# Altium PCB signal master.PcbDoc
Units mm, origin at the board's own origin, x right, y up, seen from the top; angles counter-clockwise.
Board outline 271.14 x 200.15 mm, 2 copper layers (Top Layer, Bottom Layer), stack 1.639 mm thick; 60 components, 36 nets, 314 pads, 143 vias.
Unrouted connection lines stored in the file: 4.
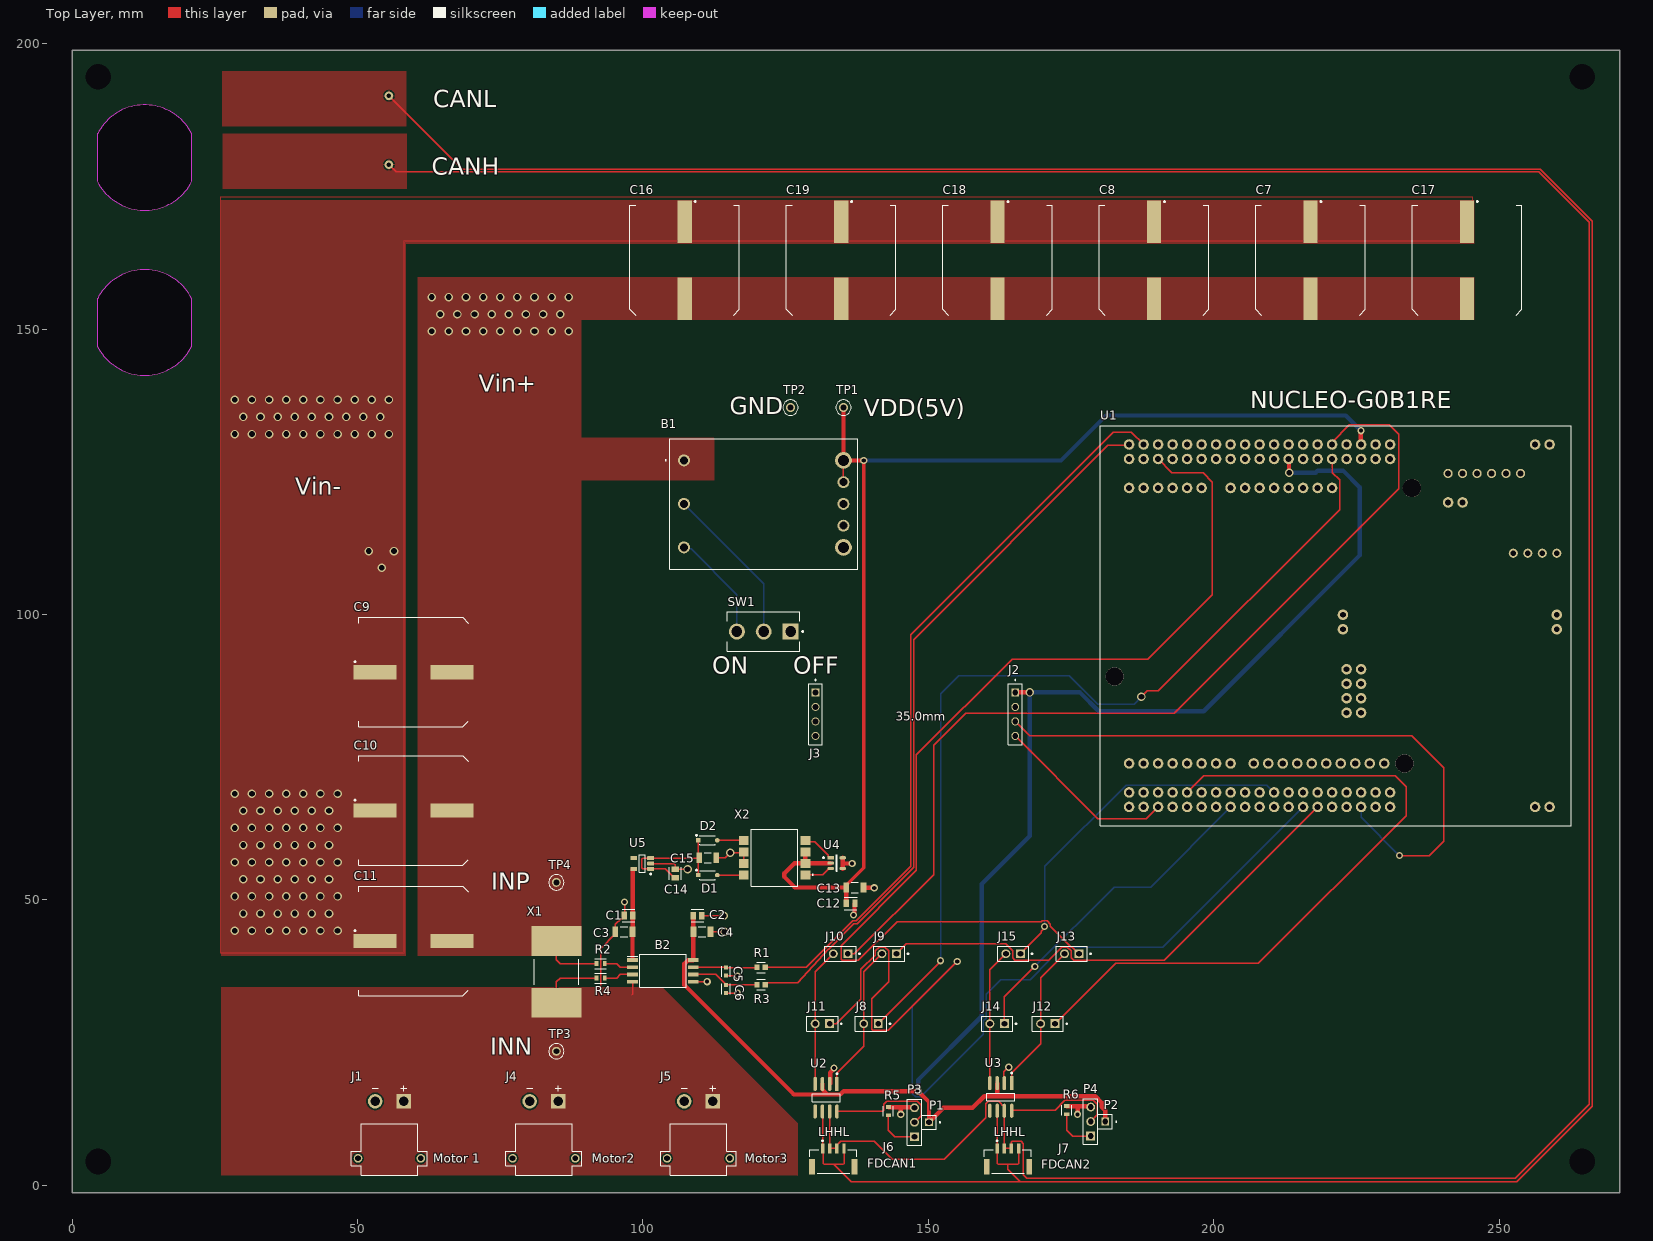
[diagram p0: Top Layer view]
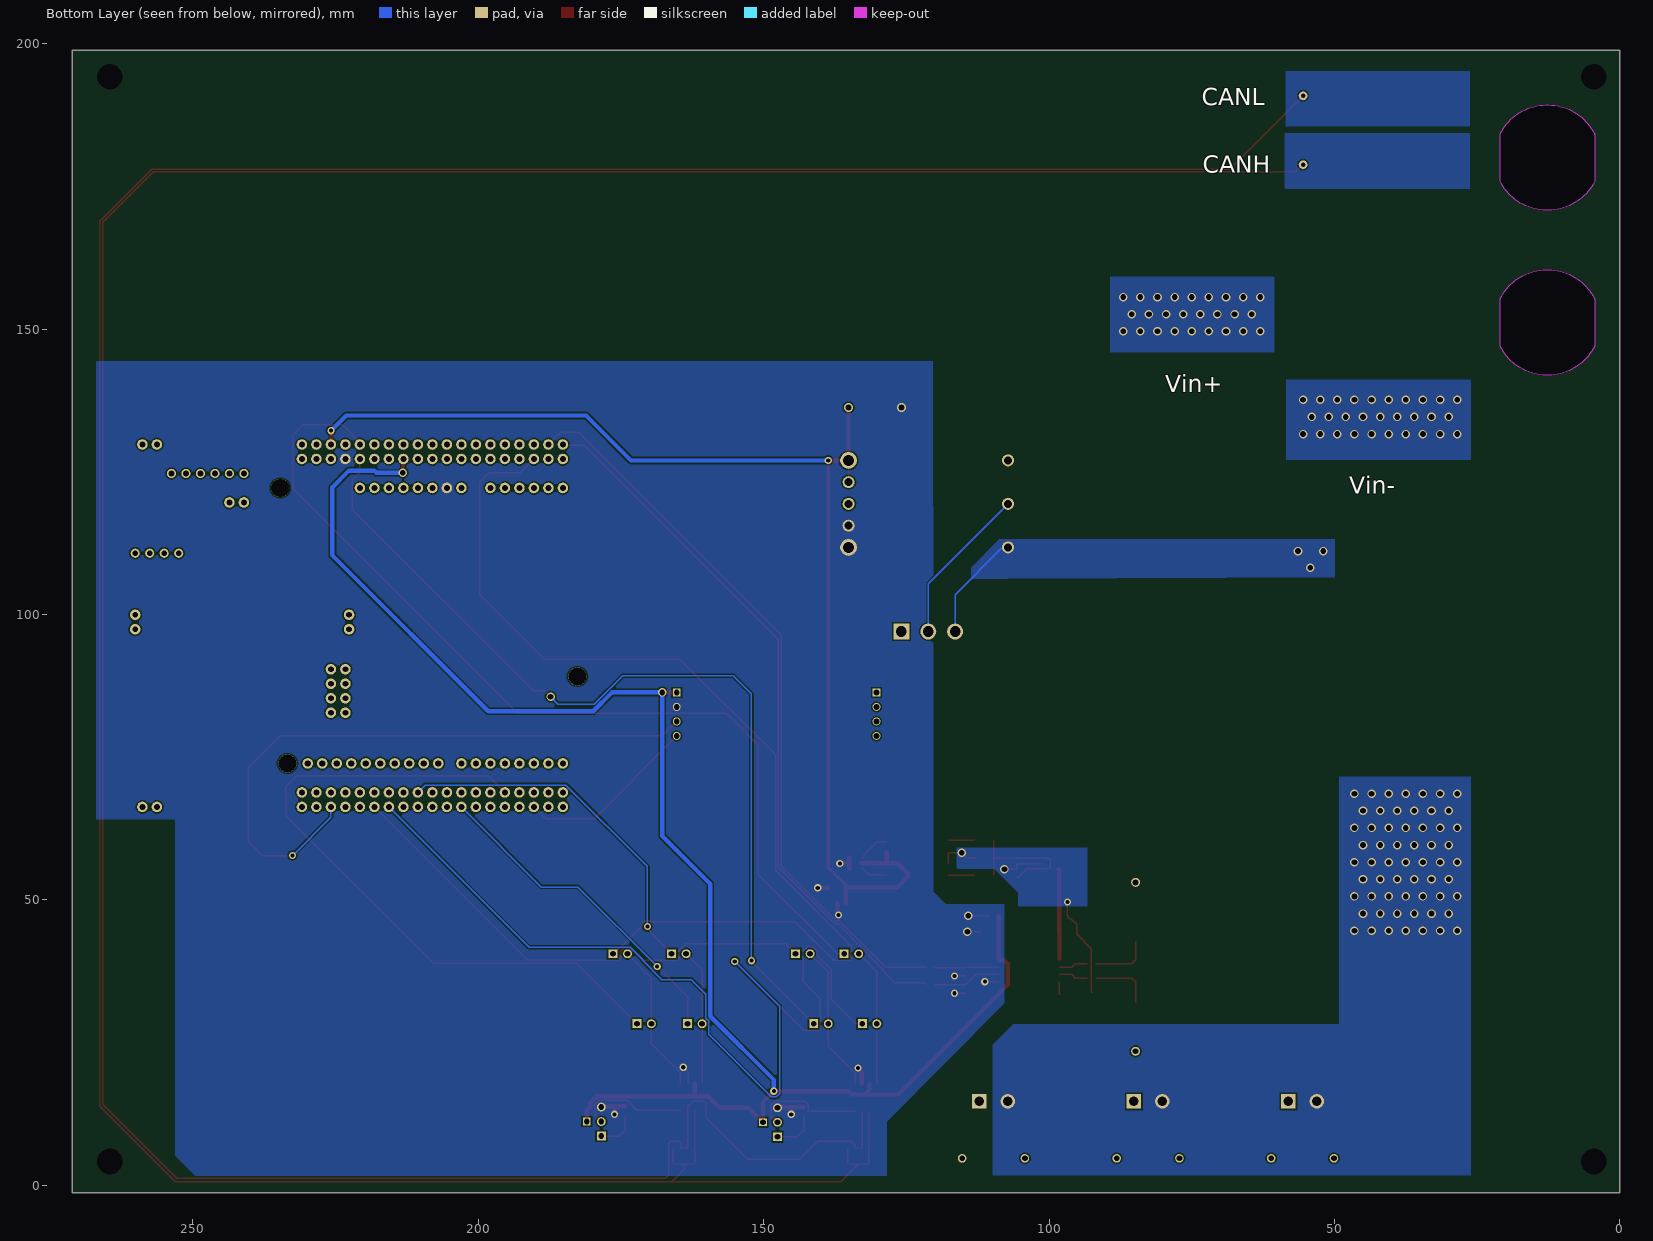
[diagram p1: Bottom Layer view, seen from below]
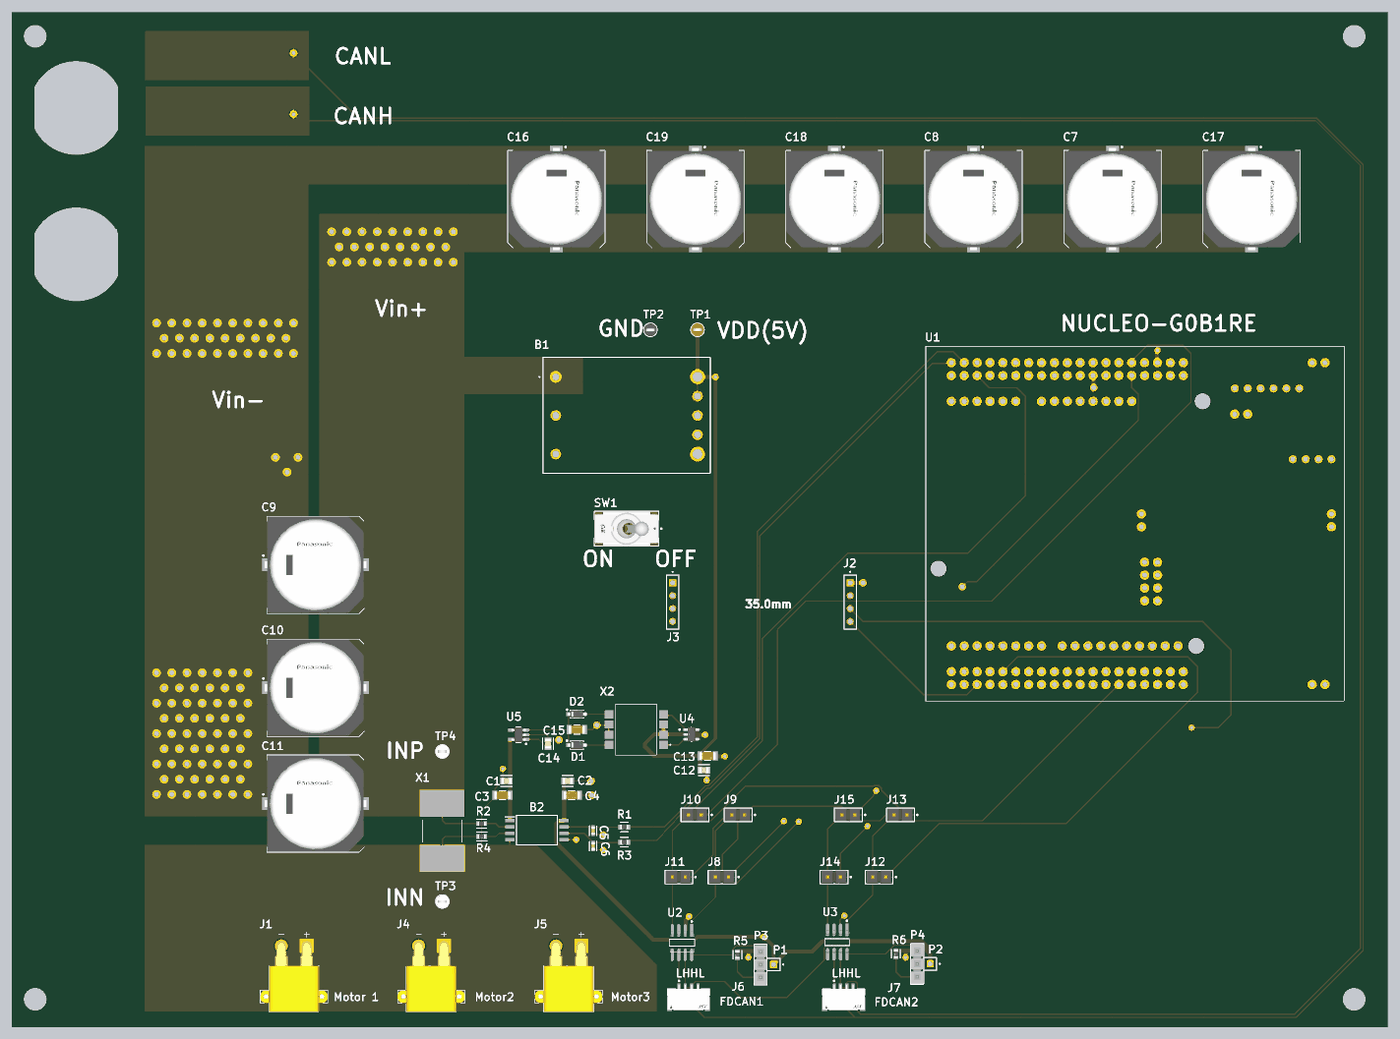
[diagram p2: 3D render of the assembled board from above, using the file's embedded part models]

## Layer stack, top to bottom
Top Solder: solder mask 0.0102, Solder Resist, Dk 3.5
Top Layer: signal copper 0.07
Dielectric 1: core 1.4986, Core-043, Dk 4.3
Bottom Layer: signal copper 0.07
Bottom Solder: solder mask 0.0102, Solder Resist, Dk 3.5

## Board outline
0,198.882 271.145,198.882 271.145,-1.27 0,-1.27
cut-out: 4.44,147.005 ccw(c12.7,151.168) 20.953,146.991 20.955,147.01 20.955,155.321 20.954,155.343 ccw(c12.7,151.168) 4.451,155.353 4.445,155.333
cut-out: 4.44,175.883 ccw(c12.7,180.046) 20.953,175.869 20.955,175.888 20.955,184.199 20.954,184.221 ccw(c12.7,180.046) 4.451,184.231 4.445,184.211

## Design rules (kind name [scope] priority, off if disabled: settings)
AssemblyTestPointUsage [All] p1: isadvanced=TRUE
AssemblyTestpoint [All] p1: isadvanced=TRUE testpointundercomponent=TRUE minsize=1.016 maxsize=2.54 preferedsize=1.524 minholesize=0 maxholesize=1.016 preferedholesize=0.813 testpointgrid=0.025 usegrid=TRUE gridtolerance=0 allowsidetop=TRUE allowsidebottom=TRUE
Clearance "Stitching Vin-" [IsStitchingVia and InNet('Vin-') vs (IsVia and (Not IsStitchingVia)) Or IsPad] p1: isadvanced=TRUE gap=0.127 ignorepadtopadclearanceinfootprint=FALSE
Clearance Clearance_1 [OnMid vs OnMid] p2: gap=0.254 ignorepadtopadclearanceinfootprint=FALSE sourcerule=55 cellrowname=All cellrowtype=0 cellcolname=All cellcoltype=0 innerlayers=TRUE
Clearance Clearance_2 [(ExistsOnLayer('Top Layer') Or ExistsOnLayer('Bottom Layer')) vs (ExistsOnLayer('Top Layer') Or ExistsOnLayer('Bottom Layer'))] p3: gap=0.254 ignorepadtopadclearanceinfootprint=FALSE sourcerule=55 cellrowname=All cellrowtype=0 cellcolname=All cellcoltype=0 outerlayers=TRUE
Clearance [All] p4: gap=0.254 ignorepadtopadclearanceinfootprint=FALSE ismatrix=TRUE
ComponentClearance [All] p1: isadvanced=TRUE gap=0.254 collisioncheckmode=3 verticalgap=0.254 showdistances=FALSE
FabricationTestPointUsage [All] p1: isadvanced=TRUE valid=0 allowmultiple=FALSE
FabricationTestpoint [All] p1: isadvanced=TRUE side=3 testpointundercomponent=TRUE minsize=1.016 maxsize=2.54 preferedsize=1.524 minholesize=0 maxholesize=1.016 preferedholesize=0.813 testpointgrid=0.025 allowsidetop=TRUE allowsidebottom=TRUE usegrid=TRUE gridtolerance=0
FanoutControl Fanout_BGA [IsBGA] p1: isadvanced=TRUE bgadir=Out bgaviamode=Centered fanoutstyle=Auto fanoutdirection=Alternating viagrid=0.025 // Fanout_BGA (Default Rule)
FanoutControl Fanout_LCC [IsLCC] p2: isadvanced=TRUE bgadir=Out bgaviamode=Centered fanoutstyle=Auto fanoutdirection=Alternating viagrid=0.025 // Fanout_LCC (Default Rule)
FanoutControl Fanout_SOIC [IsSOIC] p3: isadvanced=TRUE bgadir=Out bgaviamode=Centered fanoutstyle=Auto fanoutdirection=Alternating viagrid=0.025 // Fanout_SOIC (Default Rule)
FanoutControl Fanout_Small [(CompPinCount < 5)] p4: isadvanced=TRUE bgadir=Out bgaviamode=Centered fanoutstyle=Auto fanoutdirection=OutThenIn viagrid=0.025 // Fanout_Small (Default Rule)
FanoutControl Fanout_Default [All] p5: isadvanced=TRUE bgadir=Out bgaviamode=Centered fanoutstyle=Auto fanoutdirection=Alternating viagrid=0.025 // Fanout_Default (Default Rule)
Height [All] p1: isadvanced=TRUE minheight=0 maxheight=25.4 prefheight=12.7
HoleSize [All] p1: isadvanced=TRUE absolutevalues=TRUE maxlimit=5 minlimit=0.025 maxpercent=80.000 minpercent=20.000
HoleToHoleClearance [All] p1: isadvanced=TRUE gap=0.254 allowstackedmicrovias=TRUE
LayerPairs [All] p1: isadvanced=TRUE enforce=TRUE
MinimumSolderMaskSliver [All] p1: isadvanced=TRUE minsoldermaskwidth=0.05
NetAntennae [All] p1: isadvanced=TRUE netantennaetolerance=0
PasteMaskExpansion [All] p1: isadvanced=TRUE expansion=0
PlaneClearance [All] p1: isadvanced=TRUE clearance=0.508
PlaneConnect [All] p1: isadvanced=TRUE planeconnectstyle=Relief reliefexpansion=0.508 reliefentries=4 reliefconductorwidth=0.254 reliefairgap=0.254
PolygonConnect "Schematic Polygon Connect Style_5" [InNet('GND')] p1: connectstyle=Direct reliefconductorwidth=0.254 reliefentries=4 polygonreliefangle="90 Angle" airgapwidth=0.254
PolygonConnect "Schematic Polygon Connect Style_4" [InNet('INP')] p2: connectstyle=Direct reliefconductorwidth=0.254 reliefentries=4 polygonreliefangle="90 Angle" airgapwidth=0.254
PolygonConnect "Schematic Polygon Connect Style_3" [InNet('VDD')] p3: connectstyle=Direct reliefconductorwidth=0.254 reliefentries=4 polygonreliefangle="90 Angle" airgapwidth=0.254
PolygonConnect "Schematic Polygon Connect Style_2" [InNet('AVDD')] p4: connectstyle=Direct reliefconductorwidth=0.254 reliefentries=4 polygonreliefangle="90 Angle" airgapwidth=0.254
PolygonConnect "Schematic Polygon Connect Style_1" [InNet('Vin-')] p5: connectstyle=Direct reliefconductorwidth=0.254 reliefentries=4 polygonreliefangle="90 Angle" airgapwidth=0.254
PolygonConnect "Schematic Polygon Connect Style" [InNet('VCC')] p6: connectstyle=Direct reliefconductorwidth=0.254 reliefentries=4 polygonreliefangle="90 Angle" airgapwidth=0.254
PolygonConnect PolygonConnectStyle_1 [InNet('INN')] p7: connectstyle=Direct reliefconductorwidth=0.254 reliefentries=4 polygonreliefangle="90 Angle" airgapwidth=0.254
PolygonConnect [All] p8: connectstyle=Relief reliefconductorwidth=0.254 reliefentries=4 polygonreliefangle="90 Angle" airgapwidth=0.254
RoutingCorners [All] p1: isadvanced=TRUE cornerstyle=45-Degree minsetback=2.54 maxsetback=2.54
RoutingPriority [All] p1: isadvanced=TRUE routingpriority=0
RoutingVias [All] p1: holewidth=1 width=1.5 viastyle="Through Hole" minholewidth=1 minwidth=1.5 maxholewidth=1 maxwidth=1.5
ShortCircuit [All] p1: isadvanced=TRUE allowed=FALSE
SilkToSilkClearance [All] p1: isadvanced=TRUE silktosilkclearance=0.254
SilkToSolderMaskClearance [IsPad] p1: isadvanced=TRUE minsilkscreentomaskgap=0.1 clearancetoexposedcopper=TRUE
SolderMaskExpansion [All] p1: isadvanced=TRUE expansion=0.102 istentingtop=FALSE
SupplyNets "Schematic Supply Nets_2" [InNet('Vin-')] p1: isadvanced=TRUE voltage=0.000
SupplyNets "Schematic Supply Nets_7" [InNet('INN')] p2: isadvanced=TRUE voltage=0.000
SupplyNets "Schematic Supply Nets_4" [InNet('INP')] p3: isadvanced=TRUE voltage=0.000
SupplyNets "Schematic Supply Nets_6" [InNet('VDD')] p4: isadvanced=TRUE voltage=0.000
SupplyNets "Schematic Supply Nets_5" [InNet('GND')] p5: isadvanced=TRUE voltage=0.000
SupplyNets "Schematic Supply Nets_1" [InNet('VCC')] p6: isadvanced=TRUE voltage=0.000
SupplyNets "Schematic Supply Nets" [InNet('AVDD')] p7: isadvanced=TRUE voltage=0.000
UnRoutedNet [All] p1: isadvanced=TRUE
UnpouredPolygon [All] p1: isadvanced=TRUE
Width MaxMinWidth_2 [InNet('GND')] p1: maxlimit=1 minlimit=0.2 preferedwidth=0.6 minimp=50.000000 maximp=50.000000 favimp=50.000000
Width MaxMinWidth_1 [InNet('VDD')] p2: maxlimit=1 minlimit=0.2 preferedwidth=0.6 minimp=50.000000 maximp=50.000000 favimp=50.000000
Width MaxMinWidth_4 [InNet('AVDD')] p3: maxlimit=1 minlimit=0.2 preferedwidth=0.6 minimp=50.000000 maximp=50.000000 favimp=50.000000
Width MaxMinWidth_3 [InNet('VCC')] p4: maxlimit=1 minlimit=0.2 preferedwidth=0.6 minimp=50.000000 maximp=50.000000 favimp=50.000000
Width [All] p5: maxlimit=0.254 minlimit=0.254 preferedwidth=0.254
4 further rules are at their usual default settings.

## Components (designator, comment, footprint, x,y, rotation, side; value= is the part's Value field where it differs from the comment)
B1 "ULS-5_20-D48N-C" ULS520D48NC 107.188,127 r0 top
B2 "AMC1306M25QDWVRQ1" SOIC127P1150X280-8N 103.496,37.592 r0 top
C1 "C0805C106K8PACTU" FP-C0805C-DG-MFG 97.471,47.268 r0 top value=10uF
C2 "C0805C106K8PACTU" FP-C0805C-DG-MFG 109.539,47.261 r180 top value=10uF
C3 "CC1206KRX7R9BB104" FP-CC1206-1_25-MFG 96.671,44.45 r0 top value="100 nF"
C4 "CC1206KRX7R9BB104" FP-CC1206-1_25-MFG 110.339,44.45 r180 top value="100 nF"
C5 "CGA3E2NP01H330J080AA" FP-CGA3E-0_3-0_1-MFG 114.554,37.465 r270 top
C6 "CGA3E2NP01H330J080AA" FP-CGA3E-0_3-0_1-MFG 114.554,34.417 r270 top
C7 "EEV-TG2A221M" FP-TG-K16-MFG 216.941,162.071 r270 top
C8 "EEV-TG2A221M" FP-TG-K16-MFG 189.535,162.071 r270 top
C9 "EEV-TG2A221M" FP-TG-K16-MFG 59.817,89.916 r0 top
C10 "EEV-TG2A221M" FP-TG-K16-MFG 59.817,65.659 r0 top
C11 "EEV-TG2A221M" FP-TG-K16-MFG 59.817,42.799 r0 top
C12 "C0805C106K8PACTU" FP-C0805C-DG-MFG 136.398,49.403 r180 top value=10uF
C13 "CC1206KRX7R9BB104" FP-CC1206-1_25-MFG 137.136,52.197 r180 top value="100 nF"
C14 "C0805C106K8PACTU" FP-C0805C-DG-MFG 105.664,54.622 r90 top value=10uF
C15 "CC1206KRX7R9BB104" FP-CC1206-1_25-MFG 111.355,57.404 r0 top value="100 nF"
C16 "EEV-TG2A221M" FP-TG-K16-MFG 107.315,162.071 r270 top
C17 "EEV-TG2A221M" FP-TG-K16-MFG 244.348,162.071 r270 top
C18 "EEV-TG2A221M" FP-TG-K16-MFG 162.128,162.071 r270 top
C19 "EEV-TG2A221M" FP-TG-K16-MFG 134.722,162.071 r270 top
D1 "MBR0520LT1G" FP-425-04-IPC_C 111.339,54.356 r0 top
D2 "MBR0520LT1G" FP-425-04-IPC_C 111.339,60.452 r0 top
J1 "XT30PW-M" AMASS_XT30PW-M 55.587,4.73 r180 top
J2 "SSW-104-01-T-S" SAMTEC_SSW-104-01-T-S 165.227,86.36 r270 top
J3 "SSW-104-01-T-S" SAMTEC_SSW-104-01-T-S 130.229,86.36 r270 top
J4 "XT30PW-M" AMASS_XT30PW-M 82.658,4.73 r180 top
J5 "XT30PW-M" AMASS_XT30PW-M 109.728,4.73 r180 top
J6 "SM04B-GHS-TB(LF)(SN)" FP-SM04B-GHS-TB_LF_SN-MFG 133.35,4.191 r0 top
J7 "SM04B-GHS-TB(LF)(SN)" FP-SM04B-GHS-TB_LF_SN-MFG 163.932,4.191 r0 top
J8 "TSW-102-07-G-S" FP-TSW-102-07-G-S-MFG 139.954,28.321 r180 top
J9 "TSW-102-07-G-S" FP-TSW-102-07-G-S-MFG 143.129,40.581 r180 top
J10 "TSW-102-07-G-S" FP-TSW-102-07-G-S-MFG 134.62,40.581 r180 top
J11 "TSW-102-07-G-S" FP-TSW-102-07-G-S-MFG 131.445,28.321 r180 top
J12 "TSW-102-07-G-S" FP-TSW-102-07-G-S-MFG 170.942,28.321 r180 top
J13 "TSW-102-07-G-S" FP-TSW-102-07-G-S-MFG 175.133,40.581 r180 top
J14 "TSW-102-07-G-S" FP-TSW-102-07-G-S-MFG 162.052,28.321 r180 top
J15 "TSW-102-07-G-S" FP-TSW-102-07-G-S-MFG 164.846,40.581 r180 top
P1 "HTSW-101-07-L-S" SAMTEC_HTSW-101-07-L-S 150.114,11.049 r0 top
P2 "HTSW-101-07-L-S" SAMTEC_HTSW-101-07-L-S 180.975,11.176 r0 top
P3 "TSW-103-07-G-S" SMTC-TSW-103-07-X-S 147.574,8.509 r90 top
P4 "TSW-103-07-G-S" SMTC-TSW-103-07-X-S 178.435,8.636 r90 top
R1 "CRCW0603100RJNEA" FP-CRCW0603-e3-IPC_B 120.697,38.196 r0 top
R2 "ERJ-3GEY0R00V" FP-ERJ-3GEY0R00V-MFG 92.583,38.862 r0 top value=0Ω
R3 "CRCW0603100RJNEA" FP-CRCW0603-e3-IPC_B 120.697,35.179 r180 top
R4 "ERJ-3GEY0R00V" FP-ERJ-3GEY0R00V-MFG 92.583,36.322 r180 top value=0Ω
R5 "RMCF0603FT10K0" FP-RMCF0603-MFG 143.002,12.991 r270 top
R6 "RMCF0603FT10K0" FP-RMCF0603-MFG 174.244,13.171 r270 top
SW1 "7101SD9CQE" FP-7101SD9CQE-MFG 121.158,97.028 r270 top
TP1 "5000" FP-5000-MFG 135.128,136.271 r0 top
TP2 "5001" FP-5001-MFG 125.857,136.271 r0 top
TP3 "5002" FP-5002-MFG 84.836,23.495 r0 top
TP4 "5002" FP-5002-MFG 84.836,53.086 r0 top
U1 "NUCLEO-G0B1RE" MODULE_NUCLEO-G0B1RE 221.376,98.044 r270 top
U2 "SN65HVD230DR" FP-D0008A-IPC_A 132.08,15.368 r270 top
U3 "SN65HVD230DR" FP-D0008A-IPC_A 162.687,15.495 r270 top
U4 "SN6501DBVR" FP-DBV0005A-IPC_C 133.951,56.449 r0 top
U5 "TPS76350DBVR" DBV0005A_M 99.871,56.388 r180 top
X1 "WSLP59311L000FEB" WSLP59311L000FEB 84.836,37.404 r90 top
X2 "DA2303-ALD" DA2303ALD 123.063,57.404 r180 top

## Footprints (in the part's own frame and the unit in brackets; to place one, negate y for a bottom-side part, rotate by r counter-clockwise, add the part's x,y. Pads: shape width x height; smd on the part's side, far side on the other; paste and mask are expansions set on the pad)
AMASS_XT30PW-M [mm]
  round 2.55 hole 1.7: N(2.5,-10)
  rect 2.55x2.55 / inner round 2.55 / far side rect 2.55x2.55 hole 1.7: P(-2.5,-10)
  round 1.508 hole 1: S1(5.5,0) S2(-5.5,0)
  silkscreen extent -6.65,-12.75 6.65,2.95, body extent -6.65,-11 6.65,2.95, height 5
DA2303ALD [mm]
  rect 1.7x1.6 smd: 1(-5.4,3) 2(-5.4,1) 3(-5.4,-1) 4(-5.4,-3) 5(5.4,-3) 6(5.4,-1) 7(5.4,1) 8(5.4,3)
  silkscreen extent -6.8,-5 4.05,5
DBV0005A_M [mm] "SOT23, 5-Leads, Body 3.05x1.75mm, Pitch 0.95mm, IPC Low Density"
  rrect15% 1.2x0.65 smd: 1(-1.475,0.95) 2(-1.475,0) 3(-1.475,-0.95) 4(1.475,-0.95) 5(1.475,0.95)
  silkscreen extent -1.6,-1.55 0.5,1.95, body extent -1.42,-1.46 1.42,1.46, height 1.08
FP-425-04-IPC_C [mm]
  rect 0.808x0.742 smd paste+0 mask+0: 1(-1.68,0)
  rrect100% 0.808x0.742 smd paste+0 mask+0: 2(1.68,0)
  silkscreen extent -2.07,-0.8 1.35,1, body extent -2.18,-0.9 2.18,0.9, height 0.25
FP-5000-MFG [mm]
  round 1.57 hole 1.02 paste-2539.97 mask+0: 1(0,0)
  silkscreen extent -1.35,-1.34 1.35,1.34, body extent -1.45,-1.45 1.45,1.45, height 0.25
FP-5001-MFG [mm]
  round 1.57 hole 1.016 paste-2539.97 mask+0: 1(0,0)
  silkscreen extent -1.35,-1.34 1.35,1.34, body extent -1.45,-1.45 1.45,1.45, height 0.25
FP-5002-MFG [mm]
  round 1.57 hole 1.02 paste-2539.97 mask+0: 1(0,0)
  silkscreen extent -1.35,-1.34 1.35,1.34, body extent -1.45,-1.45 1.45,1.45, height 0.25
FP-7101SD9CQE-MFG [mm]
  rect 2.8x2.8 hole 1.85 paste-2539.97 mask+0: 1(0,4.7)
  round 2.8 hole 1.85 paste-2539.97 mask+0: 2(0,0) 3(0,-4.7)
  silkscreen extent -3.43,-6.35 3.43,6.95, body extent -3.53,-6.45 3.53,6.45, height 0.25
FP-C0805C-DG-MFG [mm]
  rect 0.95x1.35 smd paste+0 mask+0: 1(-0.75,0) 2(0.75,0)
  silkscreen extent -1.11,-1.08 1.1,1.07, body extent -1.4,-0.85 1.4,0.85, height 0.25
FP-CC1206-1_25-MFG [mm]
  rect 1x1.8 smd paste+0 mask+0: 1(-1.5,0) 2(1.5,0)
  silkscreen extent -0.63,-0.9 0.63,0.9, body extent -2.2,-1.25 2.2,1.25, height 0.25
FP-CGA3E-0_3-0_1-MFG [mm]
  rect 0.7x0.7 smd paste+0 mask+0: 1(-0.7,0) 2(0.7,0)
  silkscreen extent -0.95,-0.72 0.95,0.72, body extent -1.15,-0.65 1.15,0.65, height 0.25
FP-CRCW0603-e3-IPC_B [mm]
  rect 0.935x0.962 smd paste+0 mask+0: 1(-0.715,0) 2(0.715,0)
  silkscreen extent -0.75,-0.95 0.75,0.9, body extent -1.43,-0.73 1.43,0.73, height 0.25
FP-D0008A-IPC_A [mm]
  rect 2.469x0.622 smd paste+0 mask+0: 1(-2.414,1.905)
  rrect100% 2.469x0.622 smd paste+0 mask+0: 2(-2.414,0.635) 3(-2.414,-0.635) 4(-2.414,-1.905) 5(2.414,-1.905) 6(2.414,-0.635) 7(2.414,0.635) 8(2.414,1.905)
  silkscreen extent -4.32,-2.45 0.68,2.45, body extent -4.15,-2.95 4.15,2.95, height 0.25
FP-DBV0005A-IPC_C [mm]
  rect 1.205x0.532 smd paste+0 mask+0: 1(-1.05,0.95)
  rrect100% 1.205x0.532 smd paste+0 mask+0: 2(-1.05,0) 3(-1.05,-0.95) 4(1.05,-0.95) 5(1.05,0.95)
  silkscreen extent -2.45,-1.45 0.05,1.45, body extent -1.75,-1.55 1.75,1.55, height 0.25
FP-ERJ-3GEY0R00V-MFG [mm]
  rect 0.65x0.9 smd paste+0 mask+0: 1(-0.725,0) 2(0.725,0)
  silkscreen extent -1.03,-0.87 1.03,0.87, body extent -1.15,-0.58 1.15,0.58, height 0.25
FP-RMCF0603-MFG [mm]
  rect 0.65x0.9 smd paste+0 mask+0: 1(-0.725,0) 2(0.725,0)
  silkscreen extent -0.85,-0.88 0.85,0.88, body extent -1.15,-0.58 1.15,0.58, height 0.25
FP-SM04B-GHS-TB_LF_SN-MFG [mm]
  rect 0.6x1.7 smd paste+0 mask+0: 1(-1.875,2.275) 2(-0.625,2.275) 3(0.625,2.275) 4(1.875,2.275)
  rect 1x2.7 smd paste+0 mask+0: 5(-3.725,-0.925) 6(3.725,-0.925)
  silkscreen extent -4.13,-2.02 4.13,3.75, body extent -4.33,-2.37 4.33,3.22, height 0.25
FP-TG-K16-MFG [mm]
  rect 7.5x2.5 smd paste+0 mask+0: 1(-6.75,0) 2(6.75,0)
  silkscreen extent -10.4,-9.6 9.6,9.6, body extent -10.75,-9.85 10.75,9.85, height 0.25
FP-TSW-102-07-G-S-MFG [mm]
  rect 1.57x1.57 hole 1.02 paste-2539.97 mask+0: 1(-1.27,0)
  round 1.57 hole 1.02 paste-2539.97 mask+0: 2(1.27,0)
  silkscreen extent -3.43,-1.34 2.73,1.34, body extent -2.83,-1.44 2.83,1.44, height 0.25
MODULE_NUCLEO-G0B1RE [mm]
  round 1.6 hole 1: CN4_1(-12.7,38.72) CN4_2(-12.7,36.18) CN4_3(-12.7,33.64) CN4_4(-12.7,31.1) CN11_1(-26.67,32.37) CN11_2(-26.67,29.83) CN11_3(-26.67,27.29) CN11_4(-26.67,24.75) CN11_5(-26.67,22.21) CN11_6(-26.67,19.67)
  round 1.85 hole 1.1: CN5_1(24.13,-14.37) CN5_2(24.13,-11.83) CN5_3(24.13,-9.29) CN5_4(24.13,-6.75) CN5_5(24.13,-4.21) CN5_6(24.13,-1.67) CN5_7(24.13,0.87) CN5_8(24.13,3.41) CN5_9(24.13,5.95) CN5_10(24.13,8.49) CN6_1(-24.13,-0.65) CN6_2(-24.13,-3.19) CN6_3(-24.13,-5.73) CN6_4(-24.13,-8.27) CN6_5(-24.13,-10.81) CN6_6(-24.13,-13.35) CN6_7(-24.13,-15.89) CN6_8(-24.13,-18.43) CN8_1(-24.13,-23.51) CN8_2(-24.13,-26.05) CN8_3(-24.13,-28.59) CN8_4(-24.13,-31.13) CN8_5(-24.13,-33.67) CN8_6(-24.13,-36.21) CN9_1(24.13,-36.21) CN9_2(24.13,-33.67) CN9_3(24.13,-31.13) CN9_4(24.13,-28.59) CN9_5(24.13,-26.05) CN9_6(24.13,-23.51) CN9_7(24.13,-20.97) CN9_8(24.13,-18.43)
  round 1.85 hole 1: CN7_1(-31.75,9.51) CN7_2(-29.21,9.51) CN7_3(-31.75,6.97) CN7_4(-29.21,6.97) CN7_5(-31.75,4.43) CN7_6(-29.21,4.43) CN7_7(-31.75,1.89) CN7_8(-29.21,1.89) CN7_9(-31.75,-0.65) CN7_10(-29.21,-0.65) CN7_11(-31.75,-3.19) CN7_12(-29.21,-3.19) CN7_13(-31.75,-5.73) CN7_14(-29.21,-5.73) CN7_15(-31.75,-8.27) CN7_16(-29.21,-8.27) CN7_17(-31.75,-10.81) CN7_18(-29.21,-10.81) CN7_19(-31.75,-13.35) CN7_20(-29.21,-13.35) CN7_21(-31.75,-15.89) CN7_22(-29.21,-15.89) CN7_23(-31.75,-18.43) CN7_24(-29.21,-18.43) CN7_25(-31.75,-20.97) CN7_26(-29.21,-20.97) CN7_27(-31.75,-23.51) CN7_28(-29.21,-23.51) CN7_29(-31.75,-26.05) CN7_30(-29.21,-26.05) CN7_31(-31.75,-28.59) CN7_32(-29.21,-28.59) CN7_33(-31.75,-31.13) CN7_34(-29.21,-31.13) CN7_35(-31.75,-33.67) CN7_36(-29.21,-33.67) CN7_37(-31.75,-36.21) CN7_38(-29.21,-36.21) CN10_1(29.21,9.51) CN10_2(31.75,9.51) CN10_3(29.21,6.97) CN10_4(31.75,6.97) CN10_5(29.21,4.43) CN10_6(31.75,4.43) CN10_7(29.21,1.89) CN10_8(31.75,1.89) CN10_9(29.21,-0.65) CN10_10(31.75,-0.65) CN10_11(29.21,-3.19) CN10_12(31.75,-3.19) CN10_13(29.21,-5.73) CN10_14(31.75,-5.73) CN10_15(29.21,-8.27) CN10_16(31.75,-8.27) CN10_17(29.21,-10.81) CN10_18(31.75,-10.81) CN10_19(29.21,-13.35) CN10_20(31.75,-13.35) CN10_21(29.21,-15.89) CN10_22(31.75,-15.89) CN10_23(29.21,-18.43) CN10_24(31.75,-18.43) CN10_25(29.21,-20.97) CN10_26(31.75,-20.97) CN10_27(29.21,-23.51) CN10_28(31.75,-23.51) CN10_29(29.21,-26.05) CN10_30(31.75,-26.05) CN10_31(29.21,-28.59) CN10_32(31.75,-28.59) CN10_33(29.21,-31.13) CN10_34(31.75,-31.13) CN10_35(29.21,-33.67) CN10_36(31.75,-33.67) CN10_37(29.21,-36.21) CN10_38(31.75,-36.21) JP1_1(0.635,38.72) JP1_2(-1.905,38.72) JP2_1(15.24,4.43) JP2_2(15.24,1.89) JP2_3(12.7,4.43) JP2_4(12.7,1.89) JP2_5(10.16,4.43) JP2_6(10.16,1.89) JP2_7(7.62,4.43) JP2_8(7.62,1.89) JP3_1(-1.905,1.255) JP3_2(0.635,1.255) JP4_1(-31.75,34.91) JP4_2(-31.75,37.45) JP5_1(31.75,34.91) JP5_2(31.75,37.45) JP6_1(-21.59,19.67) JP6_2(-21.59,22.21)
  round 3.2 hole 3.2 unplated: ""(-24.13,13.32) ""(8.89,-38.75) ""(24.13,12.05)
  silkscreen extent -35,-41.25 35,41.25
SAMTEC_HTSW-101-07-L-S [mm]
  rect 1.37x1.37 / inner round 1.37 / far side rect 1.37x1.37 hole 1.02: 01(0,0)
  silkscreen extent -1.27,-1.24 2.02,1.24
SAMTEC_SSW-104-01-T-S [mm]
  rect 1.39x1.39 hole 1.04: 01(0,0)
  round 1.39 hole 1.04: 02(2.54,0) 03(5.08,0) 04(7.62,0)
  silkscreen extent -2.27,-1.21 9.15,1.21
SMTC-TSW-103-07-X-S [mm] ".025 SQ Post Terminal Strip Assembly, 1x3 Pins, Vertical, 2.54mm Pitch, Male"
  rect 1.55x1.55 hole 1.02: 1(0,0)
  round 1.55 hole 1.02: 2(2.54,0) 3(5.08,0)
  silkscreen extent -1.46,-1.27 6.54,1.27, body extent -1.27,-1.27 6.35,1.27, height 8.38
SOIC127P1150X280-8N [mm]
  rect 1.85x0.65 smd: 1(-5.325,1.905) 2(-5.325,0.635) 3(-5.325,-0.635) 4(-5.325,-1.905) 5(5.325,-1.905) 6(5.325,-0.635) 7(5.325,0.635) 8(5.325,1.905)
  silkscreen extent -6.25,-2.93 4.05,2.93
ULS520D48NC [mm]
  round 2.095 hole 1.397: 1(0,0) 2(0,-7.62) 3(0,-15.24) 5(27.94,-11.43) 6(27.94,-7.62) 7(27.94,-3.81)
  round 2.934 hole 1.956: 4(27.94,-15.24) 8(27.94,0)
  silkscreen extent -3.3,-19.07 30.47,3.81
WSLP59311L000FEB [mm]
  rect 5.2x8.75 smd: 1(-5.4,0) 2(5.4,0)
  silkscreen extent -2.25,-3.88 2.25,3.88

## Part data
B1: library part CMP-013-000001-1, "Isolated DC/DC Converters 100W 48Vin 5Vout 20A Neg Log", Manufacturer_Name="Murata Electronics", Manufacturer_Part_Number=ULS-5/20-D48N-C, Mouser Part Number=580-ULS-5/20-D48N-C
B2: library part CMP-026-000000-1, "Data Acquisition ADCs/DACs - Specialized Automotive, +/-250-mV input, precision reinforced isolated modulator with CMOS interface", Manufacturer_Name="Texas Instruments", Mouser Part Number=595-MC1306M25QDWVRQ1
C1 C2 C12 C14: library part CMP-2007-03243-2, "CAP CER 10UF 10V X5R 0805", 3DS Part Number=220-00001, Capacitance=10uF, Manufacturer=Kemet, Package=C0805C-DG, Temperature="-55°C to +85°C", Temperature Characteristic=X5R, Temperature Coefficient=15%, Temperature Range High=+85°C, Temperature Range Low=-55°C, Tolerance=10%, Voltage=10V
C3 C4 C13 C15: library part CMP-03422-000842-1, "CAP CER 0.1UF 50V X7R 1206", Capacitance="100 nF", Manufacturer=Yageo, Package=CC1206-1.25, Temperature="-55°C to +125°C", Temperature Characteristic=X7R, Temperature Coefficient=15%, Temperature Range High=+125°C, Temperature Range Low=-55°C, Tolerance=0.1, Voltage Rating="50 V"
C5 C6: library part CMP-08246-000318-1, "Cap Ceramic 33pF 50V NP0 5% Pad SMD 0603 +150°C Automotive T/R", Capacitance=33pF, Case Code (Imperial)=0603, Case Code (Metric)=1608, Dielectric=C0G, Max Operating Temperature=150°C, Min Operating Temperature=-55°C, Package Quantity=4000, Ratings=AEC-Q200, Tolerance=5%, Voltage Rating=50V
C7 C8 C9 C10 C11 C16 C17 C18 C19: library part CMP-00287-39480903-1, "Cap Aluminum 220uF 100V 20% (18 X 16.5mm) SMD 0.28 Ohm 400mA 2000 hr 125°C T/R", Capacitance=220µF, Case/Package=Radial, ESR (Equivalent Series Resistance)=280mΩ, Leakage Current=220µA, Max Operating Temperature=125°C, Min Operating Temperature=-40°C, Ripple Current=400mA, Tolerance=20%, Voltage Rating=100V
D1 D2: library part CMP-1055-00425-2, "DIODE SCHOTTKY 20V 500MA SOD123", Average Rectified Current=500mA, Case/Package=SOD-123-2, Forward Voltage=385mV, Max Forward Surge Current (Ifsm)=5.5A, Max Operating Temperature=125°C, Max Repetitive Reverse Voltage (Vrrm)=20V, Max Reverse Leakage Current=250uA, Min Operating Temperature=-65°C, Package Quantity=3000
J1 J4 J5: library part CMP-002-000003-1, "Socket; DC supply; XT30; male; PIN: 2; on PCBs; THT; Colour: yellow", Package=None
J2 J3: library part CMP-002-000002-1, "SSW - Samtec 2.54mm Single Row Straight Socket Strip 8.5 Profile - Fast Stock", Package=None
J6 J7: library part CMP-17439-000411-1, "CONN HEADER SMD R/A 4POS 1.25MM", Current Rating=1A, Housing Color=Natural, Voltage Rating=50V
J8 J9 J10 J11 J12 J13 J14 J15: library part CMP-02766-000084-1, "CONN HEADER VERT 2POS 2.54MM", Current Rating=6.3A, Manufacturer=Samtec, Temperature="-55°C to +125°C", Temperature Range High=+125°C, Temperature Range Low=-55°C, Voltage Rating=550V
P1 P2: library part CMP-030-000000-1, Package=None
P3 P4: library part CMP-1024-00333-1, "0.025\" SQ Post Header, Through-hole, Vertical, -55 to 125 degC, 2.54 mm Pitch, 3-Pin, Male, RoHS", Manufacturer=Samtec, Temperature Range="-55 to 125 degC"
R1 R3: library part CMP-2000-03827-2, "RES Thick Film, 100Ω, 5%, 0.1W, 200ppm/°C, 0603", Case Code (Imperial)=0603, Case Code (Metric)=1608, Max Operating Temperature=155°C, Max Power Dissipation=100mW, Min Operating Temperature=-55°C, Package Quantity=1, Resistance=100R, Temperature Coefficient=200ppm/°C, Tolerance=5%, Voltage Rating=75V
R2 R4: library part CMP-2000-00700-2, "RES SMD 0 OHM JUMPER 1/10W 0603", Manufacturer=Panasonic, Package=0603, Power Rating=0.1W, Resistance=0Ω, Temperature="-55°C to +155°C", Temperature Coefficient=-100/+600ppm/°C, Temperature Range High=+155°C, Temperature Range Low=-55°C, Tolerance=5%, Voltage Rating=75V
R5 R6: library part CMP-2000-06990-2, "10kΩ ±1% 0.1W 0603 Thick Film Chip Resistor AEC-Q200 compliant", Case Code (Imperial)=0603, Case Code (Metric)=1608, Max Operating Temperature=155°C, Max Power Dissipation=100mW, Min Operating Temperature=-55°C, Resistance=10kR, Resistor Type="Thick Film", Temperature Coefficient=100ppm/°C, Tolerance=1%
SW1: library part CMP-01151-55410166-1, "7101SD9CQE Toggle Switch, Spdt, On-On, Maintained, 5A, 28Vdc, 3 Pcb Hole Cnt, Solder Terminal, Toggle", Contact Current Rating=5A, Contact Resistance=10mΩ, Max Operating Temperature=85°C, Max Voltage Rating (AC)=250V, Max Voltage Rating (DC)=28V, Min Operating Temperature=-30°C, Voltage Rating (AC)=120V
TP1: library part CMP-19636-000027-1, "PC TEST POINT MINIATURE RED", Color=Red, Flammability Rating="UL94 V-0", Package Quantity=100
TP2: library part CMP-2000-05181-2, "PC TEST POINT MINIATURE BLACK", Color=Black, Flammability Rating="UL94 V-0", Package Quantity=100
TP3 TP4: library part CMP-2000-05182-2, "PC TEST POINT MINIATURE WHITE", Color=White, Flammability Rating="UL94 V-0", Package Quantity=100
U1: library part CMP-018-000001-1, "STM32G0B1RET6 Microcontroller Development Tool 0.032768MHz CPU 512KB Flash Win 7/Win 8/Win 10/Linux 64bit/Mac", Package=None
U2 U3: library part CMP-0315-00015-3, "IC TRANSCEIVER HALF 1/1 8SOIC", Case/Package=D, Max Operating Temperature=85°C, Max Supply Current=17mA, Max Supply Voltage=3.6V, Min Operating Temperature=-40°C, Min Supply Voltage=3V, Operating Supply Voltage=3.3V, Package Quantity=1
U4: library part CMP-2000-07129-2, "IC REG CONV PWR SUPPLIES SOT23-5", Case/Package=SOT-23-5, Max Input Voltage=5.5V, Max Operating Temperature=125°C, Max Output Current=350mA, Min Input Voltage=3V, Min Operating Temperature=-40°C, Operating Supply Current=300uA, Output Current=250mA, Output Voltage=11V, Package Quantity=3000, Switching Frequency=620kHz
U5: library part CMP-0394-00610-2, "Single Output LDO, 150 mA, Fixed 5 V Output, 2.7 to 10 V Input, with Low IQ, 5-pin SOT-23 (DBV), -40 to 125 degC, Green (RoHS & no Sb/Br)", Manufacturer="Texas Instruments"
X1: library part CMP-024-000000-1, "Res Metal Strip 5931 0.001 Ohm 1% 10W +/-75ppm/C Pad SMD", Manufacturer_Name=Vishay, Mouser Part Number=71-WSLP59311L000FEB
X2: library part CMP-032-000000-1, "SMT Power Transformer", Manufacturer_Name=COILCRAFT

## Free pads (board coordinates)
  round 1.524 hole 4.5 unplated: 2(4.572,4.191) 2(4.572,194.191) 2(264.57,4.191) 2(264.57,194.191)
  round 1.524 hole 0.762: 3(55.499,190.881) 4(55.499,178.816)

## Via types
v1: diameter 1.5, hole 1, Top Layer to Bottom Layer, 124 vias
v2: diameter 1.27, hole 0.711, Top Layer to Bottom Layer, 19 vias

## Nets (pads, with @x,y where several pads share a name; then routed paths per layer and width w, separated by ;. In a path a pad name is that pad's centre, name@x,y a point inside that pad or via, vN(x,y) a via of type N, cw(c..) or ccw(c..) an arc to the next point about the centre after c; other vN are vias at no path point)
AVDD: B2.1 C1.2 C3.2 U5.5 | length 15.8
  Top Layer w0.762: B2.1@98.171,39.751 C3.2 98.196,44.475 98.196,47.243 C1.2 98.221,55.382 98.277,55.438 U5.5
CAN1_RX: J10.2 J11.2 U2.4 | length 24.1
  Top Layer w0.254: U2.4 J11.2 130.175,37.406 J10.2
CAN1_RX1: J10.1 U1.CN7_9 | length 167.1
  Top Layer w0.254: J10.1 137.056,40.581 150.919,54.444 150.919,77.132 156.531,82.744 193.107,82.744 232.41,122.047 232.41,131.572 230.759,133.223 223.774,133.223 220.726,130.175 U1.CN7_9
CAN1_RX2: J11.1 U1.CN10_14 | length 174.7
  Top Layer w0.254: J11.1 133.881,28.321 138.176,32.616 138.176,37.829 140.693,40.346 140.693,41.064 141.376,41.747 142.342,41.747 143.025,41.064 143.025,35.705 140.058,32.738 140.058,27.378 140.281,27.155 142.979,27.155 v2(155.067,39.243)
  Bottom Layer w0.254: v2(155.067,39.243) 147.193,31.369 147.193,16.089 147.788,15.494 148.63,15.494 159.616,26.48 159.616,28.804 160.124,29.312 160.124,33.505 162.687,36.068 167.807,36.068 171.228,39.49 171.228,39.595 173.38,41.747 191.099,41.747 U1.CN10_14
CAN1_TX: J8.2 J9.2 U2.1 | length 26.1
  Top Layer w0.254: U2.1 133.985,19.645 138.684,24.344 J8.2 138.684,37.406 J9.2
CAN1_TX1: J8.1 U1.CN7_10 | length 159.1
  Top Layer w0.254: J8.1 152.146,39.243 v2(152.146,39.37) ; v1(187.325,85.598) 188.341,86.614 190.246,86.614 222.032,118.4 222.032,123.575 220.726,124.881 U1.CN7_10
  Bottom Layer w0.254: v2(152.146,39.37) 152.146,86.106 155.321,89.281 174.701,89.281 179.654,84.328 186.055,84.328 v1(187.325,85.598)
CAN1_TX2: J9.1 U1.CN10_12 | length 90.2
  Top Layer w0.254: J9.1 146.109,42.291 163.515,42.291 164.742,41.064 164.742,39.846 165.173,39.415 171.048,39.415 173.38,41.747 174.346,41.747 175.029,41.064 175.029,39.846 175.46,39.415 191.307,39.415 U1.CN10_12
CAN2_RX: J14.2 J15.2 U3.4 | length 23.8
  Top Layer w0.254: U3.4 J14.2 160.782,37.787 J15.2
CAN2_RX1: J14.1 U1.CN10_24 | length 58.1
  Top Layer w0.254: J14.1 163.322,33.02 v2(168.656,38.354)
  Bottom Layer w0.254: v2(168.656,38.354) 182.571,52.269 188.921,52.269 U1.CN10_24
CAN2_RX2: J15.1 U1.CN10_17 | length 63.7
  Top Layer w0.254: J15.1 169.812,44.277 169.812,44.51 170.366,45.064 v2(170.366,45.339)
  Bottom Layer w0.254: v2(170.366,45.339) 170.366,55.881 184.625,70.14 209.26,70.14 U1.CN10_17
CAN2_TX: J12.2 J13.2 U3.1 | length 26.5
  Top Layer w0.254: U3.1 164.592,19.772 169.672,24.852 J12.2 169.672,36.39 J13.2
CAN2_TX1: J12.1 U1.CN10_29 | length 122
  Top Layer w0.254: J12.1 182.798,38.907 207.817,38.907 233.68,64.77 233.68,69.85 231.775,71.755 198.247,71.755 U1.CN10_29
CAN2_TX2: J13.1 U1.CN7_34 | length 182.9
  Top Layer w0.254: J13.1 175.237,41.747 175.064,41.747 171.382,45.429 171.382,45.76 170.787,46.355 169.945,46.355 169.818,46.228 144.526,46.228 137.713,39.415 134.947,39.415 134.724,39.638 134.724,42.014 147.916,55.206 147.916,75.399 164.719,92.202 188.476,92.202 199.771,103.497 199.771,123.19 198.129,124.832 192.668,124.832 U1.CN7_34
CANH: J6.2 J6.3 J7.2 J7.3 pad.4 U2.7 U3.7 | length 536.5
  Top Layer w0.254: pad.4 56.769,177.546 60.325,177.546 256.965,177.546 265.811,168.7 265.811,14.224 252.857,1.27 167.265,1.27 166.632,1.902 166.632,7.33 166.265,7.697 164.706,7.697 164.557,7.548 J7.3 J7.2 163.315,6.473 163.315,13.074 U3.7 163.322,13.876 163.152,14.046 162.893,14.046 162.744,14.195 162.744,14.291 162.339,14.697 160.495,14.697 160.09,14.291 160.09,11.871 152.791,4.572 143.637,4.572 140.512,7.697 134.656,7.697 133.975,7.016 J6.3 J6.2 132.72,6.471 132.72,12.949 U2.7
CANL: J6.1 J6.4 J7.1 J7.4 pad.3 U2.6 U3.6 | length 550
  Top Layer w0.254: pad.3 68.326,178.054 257.175,178.054 266.319,168.91 266.319,13.843 253.111,0.635 166.116,0.635 ; U2.6 131.46,12.939 131.46,6.481 J6.1 131.572,6.369 131.572,3.832 131.721,3.683 133.413,3.683 ; J6.4 135.255,6.436 135.255,3.832 135.106,3.683 133.413,3.683 ; U3.6 162.055,13.078 162.055,6.469 J7.1 162.057,3.832 162.206,3.683 163.932,3.683 ; J7.4 165.807,3.832 165.659,3.683 163.932,3.683 ; 133.413,3.683 136.462,0.635 166.116,0.635 ; 163.932,3.683 163.932,2.819 166.116,0.635
CLK: B2.7 C5.1 R1.1 R1.2 U1.CN7_35 | length 141.1
  Top Layer w0.254: B2.7 108.852,38.196 114.523,38.196 C5.1 120.046,38.165 R1.1@120.108,38.227 ; R1.2 128.598,38.196 136.757,46.355 137.327,46.355 146.9,55.928 146.9,96.481 182.372,131.953 185.547,131.953 U1.CN7_35
DATA: B2.6 C6.1 R3.1 R3.2 U1.CN7_37 | length 138.4
  Top Layer w0.254: B2.6 112.714,36.957 C6.1 119.919,35.117 R3.2 ; R3.1 121.412,35.193 121.753,35.533 127.1,35.533 132.493,41.372 132.493,41.373 132.526,41.405 136.967,45.847 137.537,45.847 147.408,55.718 147.408,95.592 181.469,129.653 185.025,129.653 U1.CN7_37
GND: B1.4 B1.5 B2.5 C2.1 C4.1 C5.2 C6.2 C12.1 C13.1 J2.02 P3.3 P4.3 R5.1 R6.1 TP2.1 U1.CN6_7 U1.CN7_8 U2.2 U3.2 U4.4 U4.5 | length 38.5
  Top Layer w0.254: B2.5 v2(111.252,35.687) ; C2.1 114.156,47.261 v1(114.173,47.244) ; C4.1 v1(114.3,44.45) ; C6.2 114.585,33.686 116.555,33.686 v2(116.586,33.655) ; C5.2 114.585,36.734 116.555,36.734 v2(116.586,36.703) ; U3.2@163.195,17.907 163.195,19.899 163.997,20.701 v2(164.084,20.701)
  Top Layer w0.762: U2.2@132.785,17.851 132.785,19.744 133.477,20.437 v2(133.477,20.574) ; U4.4 135.001,56.449 ; U4.5 135.001,56.449 ; v2(136.652,56.388) 135.062,56.388 135.001,56.449 ; v2(136.906,47.371) 136.906,47.508 137.054,47.656 137.054,49.309 C12.1 ; C13.1 138.699,52.133 v2(140.525,52.133) ; R5.1@143.071,13.716 145.161,13.716 ; v2(145.161,12.446) 145.161,13.716 ; P3.3 147.447,13.716 145.161,13.716 ; R6.1 174.3,13.84 176.149,13.84 ; v2(176.149,12.446) 176.149,13.84 ; P4.3 178.311,13.84 176.149,13.84
  Bottom Layer w0.762: B1.4@135.128,111.506 B1.4
IMU-RX: J2.04 U1.CN10_34 | length 31.9
  Top Layer w0.254: J2.04 179.705,64.262 188.214,64.262 U1.CN10_34
IMU-TX: J2.03 U1.CN10_6 | length 111.3
  Top Layer w0.254: J2.03 167.767,78.74 234.696,78.74 240.284,73.152 240.284,60.325 237.744,57.785 v2(232.537,57.785)
  Bottom Layer w0.254: U1.CN10_6 225.806,64.516 v2(232.537,57.785)
INN: B2.3 B2.4 C1.1 C3.1 C14.2 C15.2 J1.P J4.P J5.P R4.1 R4.2 TP3.1 U5.2 X1.1 X2.6 X2.7 | length 51
  Top Layer w0.254: X1.1 84.836,35.687 85.471,36.322 R4.2 ; 92.456,33.782 92.583,33.909 92.583,41.462 95.171,44.05 C3.1 95.171,45.718 96.173,46.72 96.373,46.72 96.721,47.068 C1.1 96.774,47.321 v2(96.774,49.657) ; R4.1 95.377,36.322 96.012,36.957 B2.3 ; 98.044,33.401 98.171,33.528 B2.4 ; U5.2 105.41,56.388 105.664,56.134 C14.2 v1(107.823,55.372) ; C15.2@112.855,57.004 C15.2 114.427,57.404 v1(115.316,58.293) 117.552,58.293 117.663,58.182 X2.7
INP: B1.1 B2.2 C7.2 C8.2 C9.2 C10.2 C11.2 C16.2 C17.2 C18.2 C19.2 R2.1 R2.2 TP4.1 X1.2 | length 15.7
  Top Layer w0.254: X1.2 84.836,39.497 85.471,38.862 R2.1 ; R2.2@93.345,38.862 95.377,38.862 96.012,38.227 B2.2
  other v1: 63,149.616 66,149.616 69,149.616 72,149.616 75,149.616 78,149.616 81,149.616 84,149.616 87,149.616 64.5,152.616 67.5,152.616 70.5,152.616 73.5,152.616 76.5,152.616 79.5,152.616 82.5,152.616 85.5,152.616 63,155.616 66,155.616 69,155.616 72,155.616 75,155.616 78,155.616 81,155.616 84,155.616 87,155.616
NetB1_2: B1.2 SW1.2 | length 28.1
  Bottom Layer w0.254: B1.2 121.158,105.41 SW1.2
NetC14_1: C14.1 C15.1 D1.1 D2.1 U5.1 U5.3 | length 24.5
  Top Layer w0.254: C14.1 105.464,53.872 103.898,55.438 U5.1 100.01,55.438 99.822,55.626 99.822,57.189 99.971,57.338 U5.3 109.789,57.338 C15.1 ; D1.1 109.659,57.208 C15.1 ; D2.1 109.659,57.6 C15.1
NetD1_2: D1.2 X2.8 | length 4.7
  Top Layer w0.254: D1.2 117.615,54.356 X2.8
NetD2_2: D2.2 X2.5 | length 4.6
  Top Layer w0.254: D2.2 X2.5@117.615,60.452
NetP3_1: P3.1 R5.2 | length 7.5
  Top Layer w0.254: R5.2@143.002,12.102 143.002,9.652 144.145,8.509 P3.1
NetP3_2: P3.2 U2.8 | length 19.9
  Top Layer w0.254: U2.8 142.022,12.954 142.171,13.103 142.171,14.199 142.717,14.745 148.053,14.745 148.73,14.068 148.73,12.205 P3.2
NetP4_1: P4.1 R6.2 | length 7.2
  Top Layer w0.254: R6.2@174.244,12.229 174.244,9.652 175.26,8.636 P4.1
NetP4_2: P4.2 U3.8 | length 19.5
  Top Layer w0.254: U3.8 164.691,13.081 164.762,13.152 172.186,13.152 173.906,14.872 178.914,14.872 179.591,14.195 179.591,12.332 P4.2
NetU4_1: U4.1 X2.4 | length 5.9
  Top Layer w0.254: X2.4 128.669,60.198 130.101,60.198 132.45,57.849 132.45,57.538 132.589,57.399 U4.1
NetU4_3: U4.3 X2.1 | length 4.9
  Top Layer w0.254: X2.1 131.468,54.404 132.563,55.499 U4.3
TRIM: B1.6
VCC: B2.8 C2.2 C4.2 J2.01 P1.01 P2.01 U1.CN7_16 U2.3 U3.3 | length 288.3
  Top Layer w0.762: C2.2 108.814,47.236 108.814,44.475 C4.2 ; B2.8 108.765,39.441 107.887,39.441 107.261,38.815 107.261,35.099 126.448,15.912 132.323,15.912 ; B2.8@108.821,39.751 C4.2@108.821,44.432 ; U2.3 131.445,16.79 132.323,15.912 ; U3.3 162.052,15.761 161.925,15.634 ; J2.01 v1(167.767,86.36) ; P2.01 180.975,13.17 180.353,13.792 180.353,14.51 179.229,15.634 161.925,15.634 ; U1.CN7_16 213.169,127.191 213.169,124.904 v1(213.233,124.841) ; 132.323,15.912 134.559,15.912 135.157,16.51 v2(148.209,16.51) 150.114,14.605 P1.01 152.654,13.589 157.734,13.589 159.779,15.634 161.925,15.634
  Bottom Layer w0.762: v2(148.209,16.51) 148.209,18.475 159.362,29.628 159.362,52.809 167.767,61.214 v1(167.767,86.36) 176.544,86.36 179.846,83.058 198.247,83.058 225.552,110.363 225.552,122.301 222.631,125.222 218.222,125.222 217.841,124.841 v1(213.233,124.841)
VDD: B1.7 B1.8 C12.2 C13.2 TP1.1 U1.CN7_5 U4.2 X2.2 X2.3 | length 212.5
  Top Layer w0.254: B1.7 B1.8
  Top Layer w0.6: C13.2 135.636,52.597 138.684,55.645 v2(138.684,127)
  Top Layer w0.762: X2.3 128.463,56.494 X2.2@128.508,56.449 ; U4.2 126.553,56.449 124.776,54.672 124.776,54.04 126.619,52.197 C13.2 ; TP1.1 B1.8 v2(138.684,127) ; C13.2@135.642,52.179 135.642,49.409 C12.2 ; U1.CN7_5 225.741,129.859 225.741,132.142 v2(225.806,132.207)
  Bottom Layer w0.762: v2(138.684,127) 173.228,127 181.102,134.874 223.139,134.874 v2(225.806,132.207)
Vin-: B1.3 C7.1 C8.1 C9.1 C10.1 C11.1 C16.1 C17.1 C18.1 C19.1 J1.N J4.N J5.N SW1.3 | length 19.2
  Bottom Layer w0.254: B1.3 107.436,111.512 108.452,111.512 116.458,103.506 SW1.3
  other v1: 28.5,44.616 31.5,44.616 34.5,44.616 37.5,44.616 40.5,44.616 43.5,44.616 46.5,44.616 30,47.616 33,47.616 36,47.616 39,47.616 42,47.616 45,47.616 28.5,50.616 31.5,50.616 34.5,50.616 37.5,50.616 40.5,50.616 43.5,50.616 46.5,50.616 30,53.616 33,53.616 36,53.616 39,53.616 42,53.616 45,53.616 28.5,56.616 31.5,56.616 34.5,56.616 37.5,56.616 40.5,56.616 43.5,56.616 46.5,56.616 30,59.616 33,59.616 36,59.616 39,59.616 42,59.616 45,59.616 28.5,62.616 31.5,62.616 34.5,62.616 37.5,62.616 40.5,62.616 43.5,62.616 46.5,62.616 30,65.616 33,65.616 36,65.616 39,65.616 42,65.616 45,65.616 28.5,68.616 31.5,68.616 34.5,68.616 37.5,68.616 40.5,68.616 43.5,68.616 46.5,68.616 54.229,108.204 51.943,111.125 56.388,111.125 28.5,131.616 31.5,131.616 34.5,131.616 37.5,131.616 40.5,131.616 43.5,131.616 46.5,131.616 49.5,131.616 52.5,131.616 55.5,131.616 30,134.616 33,134.616 36,134.616 39,134.616 42,134.616 45,134.616 48,134.616 51,134.616 54,134.616 28.5,137.616 31.5,137.616 34.5,137.616 37.5,137.616 40.5,137.616 43.5,137.616 46.5,137.616 49.5,137.616 52.5,137.616 55.5,137.616
pads on no net: J1.S1 J1.S2 J3.01 J3.02 J3.03 J3.04 J4.S1 J4.S2 J5.S1 J5.S2 J6.5 J6.6 J7.5 J7.6 SW1.1 U1. U1.CN4_1 U1.CN4_2 U1.CN4_3 U1.CN4_4 U1.CN5_1 U1.CN5_2 U1.CN5_3 U1.CN5_4 U1.CN5_5 U1.CN5_6 U1.CN5_7 U1.CN5_8 U1.CN5_9 U1.CN5_10 U1.CN6_1 U1.CN6_2 U1.CN6_3 U1.CN6_4 U1.CN6_5 U1.CN6_6 U1.CN6_8 U1.CN7_1 U1.CN7_2 U1.CN7_3 U1.CN7_4 U1.CN7_6 U1.CN7_7 U1.CN7_11 U1.CN7_12 U1.CN7_13 U1.CN7_14 U1.CN7_15 U1.CN7_17 U1.CN7_18 U1.CN7_19 U1.CN7_20 U1.CN7_21 U1.CN7_22 U1.CN7_23 U1.CN7_24 U1.CN7_25 U1.CN7_26 U1.CN7_27 U1.CN7_28 U1.CN7_29 U1.CN7_30 U1.CN7_31 U1.CN7_32 U1.CN7_33 U1.CN7_36 U1.CN7_38 U1.CN8_1 U1.CN8_2 U1.CN8_3 U1.CN8_4 U1.CN8_5 U1.CN8_6 U1.CN9_1 U1.CN9_2 U1.CN9_3 U1.CN9_4 U1.CN9_5 U1.CN9_6 U1.CN9_7 U1.CN9_8 U1.CN10_1 U1.CN10_2 U1.CN10_3 U1.CN10_4 U1.CN10_5 U1.CN10_7 U1.CN10_8 U1.CN10_9 U1.CN10_10 U1.CN10_11 U1.CN10_13 U1.CN10_15 U1.CN10_16 U1.CN10_18 U1.CN10_19 U1.CN10_20 U1.CN10_21 U1.CN10_22 U1.CN10_23 U1.CN10_25 U1.CN10_26 U1.CN10_27 U1.CN10_28 U1.CN10_30 U1.CN10_31 U1.CN10_32 U1.CN10_33 U1.CN10_35 U1.CN10_36 U1.CN10_37 U1.CN10_38 U1.CN11_1 U1.CN11_2 U1.CN11_3 U1.CN11_4 U1.CN11_5 U1.CN11_6 U1.JP1_1 U1.JP1_2 U1.JP2_1 U1.JP2_2 U1.JP2_3 U1.JP2_4 U1.JP2_5 U1.JP2_6 U1.JP2_7 U1.JP2_8 U1.JP3_1 U1.JP3_2 U1.JP4_1 U1.JP4_2 U1.JP5_1 U1.JP5_2 U1.JP6_1 U1.JP6_2 U2.5 U3.5 U5.4

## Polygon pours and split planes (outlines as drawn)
GND on Bottom Layer "Bottom Layer-GND" (solid, pour order 31): 107.823,31.877 128.397,11.176 128.397,1.651 249.555,1.651 253.111,5.207 253.111,64.135 267.081,64.135 266.954,64.262 266.954,144.399 120.396,144.399 120.396,118.999 120.269,118.999 120.269,51.435 118.11,49.276 107.823,49.276 107.823,32.004
Vin- on Bottom Layer "VIN-_L02_P020" (solid, pour order 20): 107.188,106.298 107.189,106.299 113.665,106.299 113.665,108.204 108.712,113.157 49.911,113.157 49.911,106.553
CANL on Bottom Layer "CANL_L02_P030" (solid, pour order 30): 26.289,195.199 58.547,195.199 58.547,185.547 26.289,185.547
CANH on Bottom Layer "CANH_L02_P028" (solid, pour order 28): 26.289,184.277 58.674,184.277 58.674,174.625 26.289,174.625
Vin- on Bottom Layer "VIN-_L02_P027" (solid, pour order 27): 26.162,141.097 58.42,141.097 58.42,127.127 26.162,127.127
INP on Bottom Layer "INP_L02_P021" (solid, pour order 21): 60.706,159.195 60.579,159.067 60.579,145.987 89.281,145.987 89.281,159.195
INN on Bottom Layer "INN_L02_P013" (solid, pour order 13): 116.205,59.182 93.345,59.182 93.345,48.895 105.41,48.895 105.41,51.308 109.601,55.499 116.205,55.499
Vin- on Bottom Layer "Bottom Layer-Vin-" (solid, pour order 10): 26.162,1.778 109.855,1.778 109.855,28.194 49.149,28.194 49.149,71.628 26.162,71.628 26.162,26.797
INP on Top Layer "Top Layer-INP" (solid, pour order 23): 60.579,40.259 89.154,40.259 89.154,123.571 112.522,123.571 112.522,130.81 112.395,130.937 89.154,130.937 89.154,151.638 245.618,151.638 245.618,159.131 60.579,159.131
Vin- on Top Layer "Top Layer-Vin-" (solid, pour order 32): 245.364,165.481 245.364,173.101 25.908,173.101 25.908,40.767 58.166,40.767 58.166,165.481
CANH on Top Layer "CANH_L01_P018" (solid, pour order 18): 26.363,184.27 58.621,184.27 58.621,174.618 26.363,174.618
CANL on Top Layer "CANL_L01_P019" (solid, pour order 19): 26.289,195.199 58.547,195.199 58.547,185.547 26.289,185.547
Vin- on Top Layer "Top Layer-Vin-" (solid, pour order 29): 245.618,164.973 245.618,172.593 26.162,172.593 26.162,40.259 58.42,40.259 58.42,164.973
INN on Top Layer "Top Layer-INN" (solid, pour order 7): 26.162,1.778 126.926,1.778 127.127,1.651 127.127,10.922 103.378,34.671 26.162,34.671
CANH on Bottom Solder "NONET_L02_P-001" (solid): 26.289,184.277 58.674,184.277 58.674,174.625 26.289,174.625
CANL on Bottom Solder "NONET_L02_P-001" (solid): 26.289,195.199 58.547,195.199 58.547,185.547 26.289,185.547
no net on Bottom Solder "NONET_L02_P-001" (solid): 26.162,141.224 58.42,141.224 58.42,127.254 26.162,127.254
no net on Bottom Solder "NONET_L02_P-001" (solid): 60.77,159.131 60.643,159.004 60.643,145.923 89.154,145.923 89.154,159.131

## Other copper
Bottom Layer:
  pour cut-out: 110.109,28.321 110.109,24.384 106.172,28.321

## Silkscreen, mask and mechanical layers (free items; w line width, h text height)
Top Overlay:
  text "CANL" at 63.238,188.841 h3
  text "CANH" at 62.984,177.03 h3
  text "Vin+" at 71.239,139.057 h3
  text "NUCLEO-G0B1RE" at 206.367,136.136 h3
  text "GND" at 115.181,135.12 h3
  text "VDD(5V)" at 138.676,134.739 h3
  text "Vin-" at 39.108,121.023 h3
  text "ON" at 112.133,89.654 h3
  text "OFF" at 126.357,89.654 h3
  text "35.0mm" at 144.291,81.426 h1.52
  text "INP" at 73.398,51.808 h3
  text "INN" at 73.271,22.852 h3
  text "LHHL" at 130.683,8.636 h1.52
  text "LHHL" at 161.417,8.636 h1.52
  text "Motor 1" at 63.246,3.937 h1.52
  text "Motor2" at 91.059,3.937 h1.52
  text "Motor3" at 117.856,3.937 h1.52
  text "FDCAN1" at 139.319,3.048 h1.52
  text "FDCAN2" at 169.799,2.921 h1.52
Bottom Overlay:
  text "CANL" at 73.287,189.222 h3
  text "CANH" at 73.033,177.411 h3
  text "Vin+" at 79.637,138.93 h3
  text "Vin-" at 47.379,121.15 h3
Mechanical 1:
  lines w0.01: 4.186,167.286 ccw(c12.446,171.45) 20.699,167.273 ; 4.191,167.289 4.191,175.615 ; 4.197,175.635 cw(c12.446,171.45) 20.7,175.625 ; 20.701,167.292 20.701,175.603

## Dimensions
4.572,194.191 to 4.572,4.191 on Mechanical 1
4.572,4.191 to 264.57,4.191 on Mechanical 1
